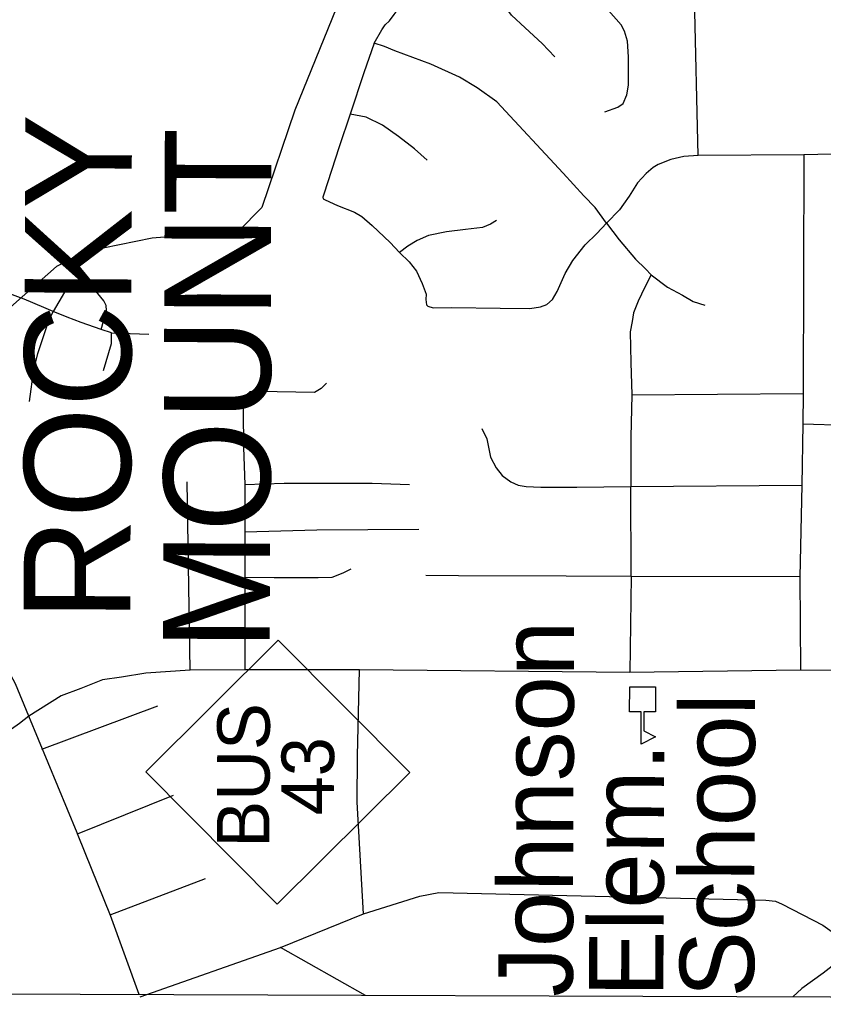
# Model space of a CAD drawing. Extents: x 2364794 to 2387902, y 795230 to 810426.
# Drawn here: x 2366649.7 to 2366996, y 800399.4 to 800821.1 of the extents above; entities that cross this region are included whole.
import ezdxf

# ---------------------------------------------------------------- set-up
doc = ezdxf.new("R2010")
doc.units = 0
for name, color, linetype in [('Default', 7, 'Continuous'), ('Plot Label CELL', 7, 'Continuous'), ('Plot Shape CELL', 7, 'Continuous')]:
    doc.layers.add(name, color=color, linetype=linetype)

msp = doc.modelspace()

# ---------------------------------------------------------------- linework, layer by layer
at = {"layer": 'Default'}
for p, q in [((2366704.07, 800497.09), (2366761.16, 800553.78)), ((2366761.16, 800553.78), (2366817.86, 800496.69)), ((2366760.76, 800439.99), (2366704.07, 800497.09)), ((2366817.86, 800496.69), (2366760.76, 800439.99))]:
    msp.add_line(p, q, dxfattribs=at)
for points in [[(2365221.07, 800406.27), (2365228.68, 802558.07), (2367168.28, 802551.22), (2367160.68, 800399.42)], [(2365221.07, 800406.27), (2365228.68, 802558.07), (2367168.28, 802551.22), (2367160.68, 800399.42)], [(2366923.65, 800533.63), (2366923.62, 800522.92), (2366918.58, 800522.94), (2366918.55, 800514.73), (2366923.69, 800512.06), (2366917.48, 800508.89), (2366917.53, 800522.94), (2366912.5, 800522.96), (2366912.54, 800533.67)]]:
    msp.add_lwpolyline(points, close=True, dxfattribs=at)
at = {"layer": 'Plot Label CELL'}
for p, q in [((2366942.02, 800762.61), (2366939.92, 800853.75)), ((2367024.2, 800763.76), (2366987.49, 800762.8)), ((2366987.49, 800762.8), (2366942.02, 800762.61)), ((2366987.49, 800762.8), (2366987.2, 800660.09)), ((2366689.29, 800686.14), (2366684.9, 800687.64)), ((2366689.29, 800686.14), (2366705.47, 800685.63)), ((2366913.44, 800659.41), (2366987.2, 800660.09)), ((2366987.2, 800660.09), (2366987.16, 800646.93)), ((2366987.16, 800646.93), (2366986.6, 800620.58)), ((2366987.16, 800646.93), (2367026.08, 800645.93)), ((2366723.19, 800540.88), (2366721.98, 800621.93)), ((2366746.8, 800620.7), (2366746.8, 800600.41)), ((2366912.99, 800619.91), (2366986.6, 800620.58)), ((2366913.16, 800581.23), (2366912.99, 800619.91)), ((2366986.6, 800620.58), (2366985.75, 800581.09)), ((2366746.8, 800600.41), (2366746.81, 800580.7)), ((2366746.81, 800580.7), (2366746.82, 800540.93)), ((2366913.16, 800581.23), (2366912.61, 800539.83)), ((2366985.75, 800581.09), (2366913.16, 800581.23)), ((2366985.75, 800581.09), (2366986.09, 800540.88)), ((2366659.29, 800506.78), (2366709.24, 800525.41)), ((2366674.65, 800470.4), (2366716.05, 800486.99)), ((2366688.83, 800435.47), (2366729.85, 800451.1)), ((2366762.17, 800421.35), (2366797.89, 800435.88)), ((2366701.64, 800400.04), (2366762.17, 800421.35))]:
    msp.add_line(p, q, dxfattribs=at)
for points in [[(2366788.16, 801000.92), (2366786.07, 800825.96), (2366768.32, 800782.08), (2366754.11, 800740.13), (2366744.07, 800730.01), (2366706.87, 800726.96), (2366678.73, 800721.27), (2366665.69, 800714.75), (2366645.89, 800697.21), (2366630.73, 800670.7), (2366626.28, 800655.17), (2366626.04, 800610.32), (2366611.08, 800601.61), (2366586.72, 800585.24), (2366554.22, 800557.13), (2366241.62, 800546.88), (2366175.9, 800494.71), (2366184.14, 800414.1)], [(2366880.22, 800805.12), (2366874.76, 800810.83), (2366867.47, 800817.55), (2366861.6, 800823.06), (2366858.36, 800827.54), (2366857.36, 800831.4), (2366857.09, 800853.07)], [(2366901.78, 800781.39), (2366907.47, 800783.4), (2366909.71, 800785.02), (2366911.35, 800788.67), (2366911.98, 800792.93), (2366912.02, 800805.11), (2366911.64, 800811.81), (2366910.23, 800816.08), (2366908.82, 800818.93), (2366903.35, 800825.04), (2366899.72, 800830.13), (2366898.81, 800832.88), (2366898.62, 800853.42)], [(2366802.53, 800810.98), (2366805.8, 800816.66), (2366807.23, 800818.88), (2366809.06, 800820.53), (2366811.11, 800823.34), (2366812.74, 800825.57), (2366814.99, 800828.6), (2366815.81, 800831.65), (2366815.77, 800851.62)], [(2366802.53, 800810.98), (2366798.02, 800798.2), (2366792.06, 800780.36)], [(2366902.52, 800733.36), (2366897.61, 800740.18), (2366892.81, 800745.17), (2366883.94, 800754.91), (2366855.24, 800785.72), (2366846.9, 800791.78), (2366839.21, 800796.3), (2366826.9, 800801.87), (2366811.35, 800807.65), (2366806.95, 800809.58), (2366802.53, 800810.98)], [(2366792.06, 800780.36), (2366787.34, 800766.36), (2366780.77, 800745.87), (2366780.35, 800744.66), (2366780.55, 800743.84), (2366781.37, 800743.44), (2366786.64, 800740.98), (2366793.94, 800738.11), (2366797.19, 800736.27), (2366801.64, 800732.4), (2366809.34, 800725.06), (2366813.39, 800720.78)], [(2366825.31, 800760.54), (2366819.84, 800765.43), (2366812.95, 800770.74), (2366806.06, 800775.64), (2366798.96, 800779.11), (2366792.06, 800780.36)], [(2366942.02, 800762.61), (2366935.9, 800762.14), (2366930.22, 800760.78), (2366924.79, 800758.75), (2366922.6, 800757.42), (2366919.57, 800754.78), (2366915.9, 800750.81), (2366912.32, 800745.11), (2366909.85, 800741.53), (2366908.12, 800739.11), (2366902.52, 800733.36)], [(2366855.19, 800734.54), (2366852.54, 800732.93), (2366849.08, 800731.52), (2366841.76, 800730.73), (2366833.63, 800729.75), (2366825.91, 800728.15), (2366821.02, 800725.93), (2366816.95, 800723.51), (2366813.39, 800720.78)], [(2366813.39, 800720.78), (2366817.54, 800716.81), (2366820.77, 800712.74), (2366823.19, 800707.45), (2366824.8, 800702.77), (2366824.79, 800700.54), (2366824.99, 800698.3), (2366825.6, 800697.69), (2366827.83, 800696.87), (2366835.96, 800697.05), (2366856.68, 800696.77), (2366869.48, 800696.72), (2366874.15, 800697.32), (2366876.8, 800698.32), (2366879.25, 800700.55), (2366881.29, 800703.99), (2366884.77, 800711.7), (2366888.04, 800717.37), (2366893.35, 800724.05), (2366898.44, 800728.91), (2366902.52, 800733.36)], [(2366902.52, 800733.36), (2366907.98, 800726.24), (2366915.06, 800717.88), (2366919.32, 800713.81), (2366921.75, 800711.16)], [(2366664.27, 800695.42), (2366660.13, 800697.05), (2366651.79, 800700.7), (2366641.04, 800704.54), (2366627.46, 800707.27), (2366614.99, 800708.48), (2366579.9, 800709.63)], [(2366921.75, 800711.16), (2366919.09, 800705.89), (2366916.22, 800699.81), (2366914.17, 800694.74), (2366913.55, 800691.09), (2366912.72, 800686.62), (2366913.08, 800673.42), (2366913.44, 800659.41)], [(2366921.75, 800711.16), (2366928.84, 800705.86), (2366935.33, 800702.38), (2366939.79, 800699.72), (2366944.86, 800698.08)], [(2366684.9, 800687.64), (2366687.25, 800695.76), (2366687.01, 800697.94), (2366686.1, 800699.89), (2366683.47, 800703.17), (2366679.07, 800706.17), (2366675.99, 800707.02), (2366674.02, 800707.23), (2366671.65, 800705.9), (2366669.04, 800703.7), (2366664.27, 800695.42)], [(2366664.27, 800695.42), (2366662.37, 800691.84), (2366657.45, 800677.15), (2366655.75, 800670.34), (2366653.9, 800656.56)], [(2366684.9, 800687.64), (2366676.34, 800690.6), (2366670.26, 800692.86), (2366664.27, 800695.42)], [(2366685.93, 800669.94), (2366689.33, 800681.57), (2366689.29, 800686.14)], [(2366781.9, 800664.44), (2366779.66, 800662.22), (2366776.81, 800660.4), (2366768.68, 800660.63), (2366752.63, 800660.89), (2366748.97, 800660.7), (2366747.55, 800659.49), (2366746.32, 800657.26), (2366746.1, 800652.59), (2366746.25, 800636.95), (2366746.8, 800620.7)], [(2366913.44, 800659.41), (2366913.07, 800641.24), (2366912.99, 800619.91)], [(2366848.78, 800645.02), (2366851, 800640.54), (2366852.59, 800632.62), (2366855.01, 800627.94), (2366857.64, 800624.68), (2366861.29, 800622.03), (2366864.54, 800620.59), (2366867.99, 800619.97), (2366874.29, 800619.75), (2366889.73, 800619.69), (2366912.99, 800619.91)], [(2366817.71, 800620.66), (2366801.66, 800621.32), (2366763.66, 800621.25), (2366746.8, 800620.7)], [(2366746.8, 800600.41), (2366777.82, 800601.3), (2366821.7, 800601.55)], [(2366792.39, 800584.4), (2366788.92, 800582.58), (2366784.25, 800580.77), (2366778.35, 800580.59), (2366759.46, 800580.66), (2366746.81, 800580.7)], [(2366913.16, 800581.23), (2366885.12, 800581.33), (2366838.8, 800581.49), (2366824.68, 800581.64)], [(2367161.3, 800576.19), (2367153.9, 800576.1), (2367145.34, 800575.49), (2367141.02, 800574.98), (2367133.16, 800573.84), (2367120.25, 800569.77), (2367101.73, 800562.89), (2367062.76, 800548.06), (2367054.62, 800544.88), (2367048.31, 800543.09), (2367043.07, 800542.14), (2367026.06, 800540.6), (2366986.09, 800540.88), (2366912.61, 800539.83), (2366796.19, 800541.03), (2366746.82, 800540.93), (2366723.19, 800540.88), (2366704.15, 800539.53), (2366693.58, 800537.8), (2366685.45, 800536.61), (2366676.09, 800532.99), (2366667.68, 800529.77), (2366653.77, 800520.95)], [(2366797.89, 800435.88), (2366795.18, 800483.97), (2366795.25, 800503.87), (2366796.19, 800541.03)], [(2366653.77, 800520.95), (2366649.72, 800517.93), (2366646.26, 800515.41), (2366640.8, 800509.62), (2366635.33, 800504.2), (2366631.14, 800498.77), (2366624.76, 800490.09), (2366615.09, 800475.24), (2366606.32, 800461.12), (2366596.04, 800444.87), (2366569.33, 800401.51)], [(2366797.89, 800435.88), (2366822.09, 800443.52), (2366830.39, 800445.12), (2366971.2, 800441.72), (2366975.35, 800441.31), (2366978.21, 800440.05), (2366995.77, 800431.01), (2367004.13, 800424.95), (2367005.02, 800423.43), (2367005.68, 800421.47), (2367005.7, 800419.06), (2367004.86, 800417.29), (2366995.88, 800410.32), (2366986.66, 800403.73), (2366982.81, 800400.05)], [(2366798.68, 800400.7), (2366762.17, 800421.35)]]:
    msp.add_lwpolyline(points, dxfattribs=at)
at = {"layer": 'Plot Shape CELL'}
for points in [[(2366653.77, 800520.95), (2366648.04, 800534.92), (2366615.14, 800595.55), (2366611.86, 800601.58), (2366604.32, 800614.61), (2366599.07, 800623.7), (2366594.77, 800632.78), (2366591.01, 800642.13), (2366588.06, 800651.22), (2366585.39, 800660.84), (2366584.59, 800664.77), (2366583.52, 800669.1), (2366581.46, 800680.28), (2366580.54, 800688.94), (2366579.89, 800697.34), (2366579.78, 800704.65), (2366579.89, 800709.28)], [(2366701.27, 800401.04), (2366688.95, 800435.14), (2366677.94, 800462.12), (2366674.65, 800470.4), (2366674.52, 800470.72), (2366653.77, 800520.95)]]:
    msp.add_lwpolyline(points, dxfattribs=at)

# ---------------------------------------------------------------- texts
at = {"layer": 'Default'}
for s, height, p in [('ROCKY', 45.927, (2366697.39, 800561.9)), ('MOUNT', 45.927, (2366757.46, 800549.19)), ('Johnson', 32.036, (2366887.98, 800400.09)), ('School', 32.036, (2366966.06, 800399.81)), ('BUS', 22.639, (2366757.35, 800464.35)), ('43', 22.639, (2366785.12, 800478.27)), ('Elem.', 32.036, (2366927.02, 800399.95))]:
    msp.add_text(s, height=height, rotation=89.7976, dxfattribs=at).set_placement(p)

doc.saveas('drawing.dxf')
